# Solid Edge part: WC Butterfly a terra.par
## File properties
Title: WC BUTTERFLY A TERRA
Author: DESYS
Template: Iso Part.par
Last saved by: PIM_1
Revision: 17
Application: Solid Edge
Tipo di contenuto documento: 0
Accuracy: 0,990
Document Number: 4008
Revision: 0
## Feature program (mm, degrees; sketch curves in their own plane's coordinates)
sketch for "unnamed Protrusion 1" plane through (10.8674, 0, 10.8674) normal (0, -1, 0) x-axis (1, 0, 0)
  line (-193.3674, -268.3674) -> (171.6326, -268.3674)
  line (171.6326, -268.3674) -> (171.6326, 216.6326)
  arc centre (131.6326, 216.6326) radius 40 from (131.6326, 256.6326) to (171.6326, 216.6326) cw
  line (131.6326, 256.6326) -> (-153.3674, 256.6326)
  arc centre (-153.3674, 216.6326) radius 40 from (-193.3674, 216.6326) to (-153.3674, 256.6326) cw
  line (-193.3674, 216.6326) -> (-193.3674, -268.3674)
  dimension (linear) = 193.3674
extrude "unnamed Protrusion 1" add finite 40 along -normal
sketch for "ProtrusioneEstrusa_2" plane through (0, 420, 0) normal (0, -1, 0) x-axis (1, 0, 0)
  line (-72.5, 142.5) -> (72.5, 142.5)
  arc centre (72.5, 102.5) radius 40 from (72.5, 142.5) to (112.5, 102.5) cw
  line (112.5, 102.5) -> (112.5, -257.5)
  line (112.5, -257.5) -> (-112.5, -257.5)
  line (-112.5, -257.5) -> (-112.5, 102.5)
  arc centre (-72.5, 102.5) radius 40 from (-112.5, 102.5) to (-72.5, 142.5) cw
  dimension (linear) = 112.5
extrude "ProtrusioneEstrusa_2" add finite 35 along +normal  Profile_Plane1_Distance = 420 mm
sketch for "ProtrusioneEstrusa_3" plane through (0, 0, 0) normal (1, 0, 0) x-axis (0, 1, 0)
  line (40, -257.5) -> (385, -257.5)
  line (385, 122.5) -> (385, -257.5)
  arc centre (364.5582, 396.4689) radius 274.7305 from (170, 202.5) to (385, 122.5) ccw
  arc centre (48.0094, 60.3605) radius 187.3108 from (40, 247.5) to (170, 202.5) cw
  line (40, 247.5) -> (40, -257.5)
extrude "ProtrusioneEstrusa_3" add finite 325 symmetric
sketch for "unnamed Cutout 1" plane through (0, 210, -257.5) normal (0, 0, -1) x-axis (1, 0, 0)
  line (-92.5, -175) -> (-205.9935, -175)
  line (-162.5, 170) -> (-92.5, -175)
  line (-162.5, 170) -> (-200.7213, 170)
extrude "unnamed Cutout 1" cut through along -normal
mirror "unnamed Mirror 1" of "unnamed Cutout 1" about plane through (0, 0, 0) normal (1, 0, 0)
extrude "unnamed Cutout 2" cut through
fillet "Rotondo_2" radius 30  VertexRadius1 = 30 mm; VertexRadius2 = 55 mm
mirror "unnamed Mirror 2" of "Rotondo_2" about plane through (0, 0, 0) normal (1, 0, 0)
fillet "unnamed Round 1"
fillet "Rotondo_4" radius 25
fillet "Rotondo_5" radius 30
fillet "Rotondo_6" radius 10
sketch for "ScavoEstrusione_3" plane through (0, 0, 0) normal (0, -1, 0) x-axis (0, 0, 1)
  line (-67.5, -137.5) -> (192.5, -137.5)
  arc centre (192.5, -107.5) radius 30 from (192.5, -137.5) to (222.5, -107.5) ccw
  line (222.5, -107.5) -> (222.5, 107.5)
  arc centre (192.5, 107.5) radius 30 from (192.5, 137.5) to (222.5, 107.5) cw
  line (192.5, 137.5) -> (-67.5, 137.5)
  arc centre (-67.5, 107.5) radius 30 from (-67.5, 137.5) to (-97.5, 107.5) ccw
  line (-97.5, 107.5) -> (-97.5, -107.5)
  arc centre (-67.5, -107.5) radius 30 from (-97.5, -107.5) to (-67.5, -137.5) ccw
extrude "ScavoEstrusione_3" cut finite 90 along -normal  Treatment1_DraftAngle = 10 deg
lofted cutout "unnamed LoftedCutout 1"
sketch for "ScavoEstrusione_4" plane through (0, 210, -257.5) normal (0, 0, -1) x-axis (1, 0, 0)
  line (97.5, -210) -> (97.5, -183.2591)
  arc centre (122.6454, -152.1511) radius 40 from (97.5, -183.2591) to (83.4442, -144.1973) cw
  line (83.4442, -144.1973) -> (142.9948, 149.3023)
  arc centre (187.0962, 140.3542) radius 45 from (167.5, 180.8633) to (142.9948, 149.3023) ccw
  line (167.5, 195) -> (167.5, 180.8633)
  line (167.5, 195) -> (-167.5, 195)
  line (-167.5, 195) -> (-167.5, 180.8633)
  arc centre (-187.0962, 140.3542) radius 45 from (-142.9948, 149.3023) to (-167.5, 180.8633) ccw
  line (-142.9948, 149.3023) -> (-83.4442, -144.1973)
  arc centre (-122.6454, -152.1511) radius 40 from (-83.4442, -144.1973) to (-97.5, -183.2591) cw
  line (-97.5, -183.2591) -> (-97.5, -210)
extrude "ScavoEstrusione_4" cut finite 125 along -normal
sketch for "ScavoEstrusione_5" plane through (0, 217.5, -132.5) normal (0, 0, -1) x-axis (1, 0, 0)
  line (-97.5, -175.7591) -> (-97.5, -202.5)
  arc centre (-122.6454, -144.6511) radius 40 from (-83.4442, -136.6973) to (-97.5, -175.7591) cw
  line (-123.9672, 63.0233) -> (-83.4442, -136.6973)
  arc centre (-47.5, 127.4653) radius 100 from (-123.9672, 63.0233) to (-50.1353, 27.5) ccw
  line (-50.1353, 27.5) -> (44.8648, 27.5)
  arc centre (47.5, 127.4653) radius 100 from (44.8648, 27.5) to (123.9672, 63.0233) ccw
  line (83.4442, -136.6973) -> (123.9672, 63.0233)
  arc centre (122.6454, -144.6511) radius 40 from (97.5, -175.7591) to (83.4442, -136.6973) cw
  line (97.5, -202.5) -> (97.5, -175.7591)
extrude "ScavoEstrusione_5" cut finite 175 along -normal
fillet "Rotondo_7" radius 30
fillet "Rotondo_8" radius 10  Radii2 = 10 mm
fillet "Rotondo_9" radius 60
sketch for "unnamed Protrusion 2" #1 plane through (0, 210, -257.5) normal (0, 0, -1) x-axis (1, 0, 0)
  line (-87.5, -210) -> (-83.4442, -144.1973)
  line (-83.4442, -144.1973) -> (-91.6082, -144.1973)
  line (-91.6082, -144.1973) -> (-97.0298, -168.4595)
  line (-97.0298, -168.4595) -> (-100.685, -182.4226)
  line (-100.685, -182.4226) -> (-100.685, -210)
  line (-87.5, -210) -> (-100.685, -210)
sketch for "unnamed Protrusion 2" #2 plane through (0, 210, -257.5) normal (0, 0, -1) x-axis (1, 0, 0)
  line (87.5, -210) -> (83.4442, -144.1973)
  line (83.4442, -144.1973) -> (91.6082, -144.1973)
  line (91.6082, -144.1973) -> (97.0298, -168.4595)
  line (97.0298, -168.4595) -> (100.685, -182.4226)
  line (100.685, -182.4226) -> (100.685, -210)
  line (87.5, -210) -> (100.685, -210)
extrude "unnamed Protrusion 2" add through along -normal
sketch for "ScavoEstrusione_6" plane through (0, 420, -57.5) normal (0, 1, 0) x-axis (1, 0, 0)
  line (-87.5, -100) -> (87.5, -100)
  line (87.5, -100) -> (87.5, -145)
  arc centre (62.5, -145) radius 25 from (62.5, -170) to (87.5, -145) ccw
  line (62.5, -170) -> (-62.5, -170)
  arc centre (-62.5, -145) radius 25 from (-87.5, -145) to (-62.5, -170) ccw
  line (-87.5, -145) -> (-87.5, -100)
extrude "ScavoEstrusione_6" cut finite 70 along -normal
replace surface "unnamed ReplaceSurface 1"
replace surface "unnamed ReplaceSurface 2"
sketch for "ProtrusioneEstrusa_7" plane through (0, 210, -257.5) normal (0, 0, -1) x-axis (1, 0, 0)
  line (-87.5, -210) -> (87.5, -210)
  line (86.2673, -190) -> (87.5, -210)
  line (-86.2673, -190) -> (86.2673, -190)
  line (-86.2673, -190) -> (-87.5, -210)
extrude "ProtrusioneEstrusa_7" add finite 30 along -normal
sketch for "ProtrusioneEstrusa_8" plane through (0, 410, -57.5) normal (0, 1, 0) x-axis (1, 0, 0)
  line (-35, -150) -> (35, -150)
  arc centre (35, -130) radius 20 from (55, -130) to (35, -150) cw
  line (55, -130) -> (55, -30)
  arc centre (35, -30) radius 20 from (35, -10) to (55, -30) cw
  line (35, -10) -> (-35, -10)
  arc centre (-35, -30) radius 20 from (-55, -30) to (-35, -10) cw
  line (-55, -30) -> (-55, -130)
  arc centre (-35, -130) radius 20 from (-35, -150) to (-55, -130) cw
  dimension (linear) = 35
  dimension (linear) = 55
extrude "ProtrusioneEstrusa_8" add through along -normal  Profile_Plane1_Distance = 10 mm; Treatment1_DraftAngle = 5 deg
fillet "Rotondo_10" radius 60
sketch for "ProtrusioneEstrusa_9" plane through (0, 210, -142.5) normal (0, 0, -1) x-axis (1, 0, 0)
  circle centre (0, -30.1) radius 50
extrude "ProtrusioneEstrusa_9" add through along -normal  Profile_Plane1_Distance = 115 mm
sketch for "ProtrusioneEstrusa_10" plane through (0, 210, -237.5) normal (0, 0, -1) x-axis (1, 0, 0)
  line (-40, 155) -> (-40, 186.0971)
  line (40, 155) -> (40, 186.0971)
extrude "ProtrusioneEstrusa_10" add through along -normal  Profile_Plane1_Distance = 20 mm
sketch for "ScavoEstrusione_7" plane through (0, 55, -237.5) normal (0, 0, -1) x-axis (1, 0, 0)
  circle centre (0, 0) radius 27.5
extrude "ScavoEstrusione_7" cut finite 70 along -normal
sketch for "ScavoEstrusione_8" plane through (0, 240.1, -142.5) normal (0, 0, -1) x-axis (1, 0, 0)
  circle centre (0, 0) radius 40
extrude "ScavoEstrusione_8" cut finite 105 along -normal
sketch for "ScavoEstrusione_9" plane through (0, 180, 52.5) normal (0, -1, 0) x-axis (0, 0, 1)
  line (20, -50) -> (-55, -50)
  arc centre (-55, -35) radius 15 from (-70, -35) to (-55, -50) ccw
  line (-70, -35) -> (-70, 35)
  arc centre (-55, 35) radius 15 from (-55, 50) to (-70, 35) ccw
  line (-55, 50) -> (20, 50)
extrude "ScavoEstrusione_9" cut finite 150 along -normal
sketch for "unnamed Cutout 3" plane through (0, 330, 35.1247) normal (0, -1, 0) x-axis (0, 0, 1)
  line (-72.6247, 40) -> (-85.0909, 40)
  line (-85.0909, 40) -> (-85.0909, -40)
  line (-85.0909, -40) -> (-72.6247, -40)
  line (-72.6247, -40) -> (-72.6247, 40)
extrude "unnamed Cutout 3" cut to key point along +normal
sketch for "ScavoEstrusione_11" plane through (0, 275.05, -37.5) normal (0, 0, -1) x-axis (1, 0, 0)
  line (-34.546, -42.1793) -> (34.546, -42.1793)
  line (34.546, -42.1793) -> (34.546, -54.1793)
  line (34.546, -54.1793) -> (-34.546, -54.1793)
  line (-34.546, -42.1793) -> (-34.546, -54.1793)
extrude "ScavoEstrusione_11" cut finite 30 along -normal
fillet "Rotondo_11" radius 20
sketch for "unnamed Protrusion 3" plane through (0, 210, -257.5) normal (0, 0, -1) x-axis (1, 0, 0)
  line (-107.5, 195) -> (-127.919, 75)
  dimension (linear) = 127.919
extrude "unnamed Protrusion 3" add through along -normal
mirror "unnamed Mirror 3" of "unnamed Protrusion 3" about plane through (0, 0, 0) normal (1, 0, 0)
extrude "unnamed Protrusion 4" add through
fillet "Rotondo_12" radius 10
fillet "Rotondo_13" radius 10
fillet "Rotondo_14" radius 30
fillet "Rotondo_15" radius 3
fillet "Rotondo_16" radius 20
fillet "Rotondo_17" radius 30
fillet "Rotondo_18" radius 20
fillet "Rotondo_19" radius 5
fillet "Rotondo_20" radius 3
fillet "Rotondo_21" radius 30
fillet "Rotondo_22" radius 15
fillet "Rotondo_23" radius 10
sketch for "Foro_1" plane through (0, 0, -3.5) normal (0, -1, 0) x-axis (0, 0, 1)
  hole centre (-159, -77.5) bore radius 7.5
hole "Foro_1" diameter 15 finite
sketch for "unnamed Hole 1" plane through (0, 0, -3.5) normal (0, -1, 0) x-axis (0, 0, 1)
  hole centre (-159, 77.5) bore radius 7.5
hole "unnamed Hole 1" finite
pattern "unnamed Pattern 1" of "Foro_1", "unnamed Hole 1"
fillet "Rotondo_24" radius 3
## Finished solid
Body 1: solid body, 254 faces, 607 edges, 359 vertices.
  Faces by surface: cylinder 84, blend 59, plane 57, torus 35, spline 9, cone 8, sphere 2
  Edges by curve: line 220, circle 204, intersection 125, curve on surface 40, ellipse 18
Bounding box of the edges (mm; curved faces can reach further): 365.000 x 420.000 x 525.000, from (-182.5, 0, -257.5) to (182.5, 420, 267.5).
Cylindrical faces by radius (mm): R3 x19, R5 x2, R7.5 x2, R10 x19, R15 x2, R20 x6, R25 x5, R27.5 x1, R30 x9, R40 x8, R50 x2, R60 x5, R100 x2, R187.3108 x1, R274.7305 x1
Conical faces (half-angle, radius in mm at the cone's reference point): 5 deg R20 x4, 10 deg R30 x4
Toroidal faces (ring radius, tube radius in mm): R7 r3 x6, R10.5 r3 x2, R13 r3 x2, R28 r3 x2, R30 r10 x2, R33 r3 x4, R35 r5 x1, R37 r3 x4, R38.391 r10 x4, R40 r10 x1, R40 r60 x2, R45 r5 x1, R60 r20 x2, R70 r60 x2
Spherical faces by radius (mm): R3 x2
Planar faces by outward normal: +x 6, +y 6, +z 7, -x 6, -y 7, -z 9, oblique 16
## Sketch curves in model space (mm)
arc centre (0, 81.9548, 2.1758) radius 100 from (0, 90, -97.5) through (0, 148.3912, -72.5651) to (0, 180, -17.5)
arc centre (0, 80.0013, 123.0011) radius 100 from (0, 90, 222.5) through (0, 156.2723, 187.6751) to (0, 180, 122.5)
arc centre (47.5, 90.0347, 0) radius 90 from (50, 180, 0) through (112.0295, 152.7718, 0) to (137.5, 90, 0)
arc centre (-47.5, 90.0347, 0) radius 90 from (-137.5, 90, 0) through (-112.0295, 152.7718, 0) to (-50, 180, 0)
arc centre (0, 180, 72.5) radius 50 from (-50, 180, 72.5) through (1.4817, 180, 122.478) to (50, 180, 72.5)
line (50, 180, 72.5) -> (50, 180, -2.5)
arc centre (35, 180, -2.5) radius 15 from (35, 180, -17.5) through (45.9106, 180, -12.7936) to (50, 180, -2.5)
line (35, 180, -17.5) -> (-35, 180, -17.5)
arc centre (-35, 180, -2.5) radius 15 from (-50, 180, -2.5) through (-45.2936, 180, -13.4106) to (-35, 180, -17.5)
line (-50, 180, -2.5) -> (-50, 180, 72.5)
arc centre (107.5, 90, -67.5) radius 30 from (107.5, 90, -97.5) through (129.3212, 90, -88.0872) to (137.5, 90, -67.5)
line (137.5, 90, -67.5) -> (137.5, 90, 192.5)
arc centre (107.5, 90, 192.5) radius 30 from (137.5, 90, 192.5) through (128.0872, 90, 214.3212) to (107.5, 90, 222.5)
line (107.5, 90, 222.5) -> (-107.5, 90, 222.5)
arc centre (-107.5, 90, 192.5) radius 30 from (-107.5, 90, 222.5) through (-129.3212, 90, 213.0872) to (-137.5, 90, 192.5)
line (-137.5, 90, 192.5) -> (-137.5, 90, -67.5)
arc centre (-107.5, 90, -67.5) radius 30 from (-137.5, 90, -67.5) through (-128.0872, 90, -89.3212) to (-107.5, 90, -97.5)
line (-107.5, 90, -97.5) -> (107.5, 90, -97.5)
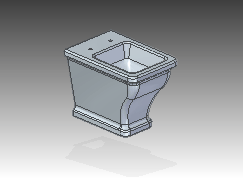
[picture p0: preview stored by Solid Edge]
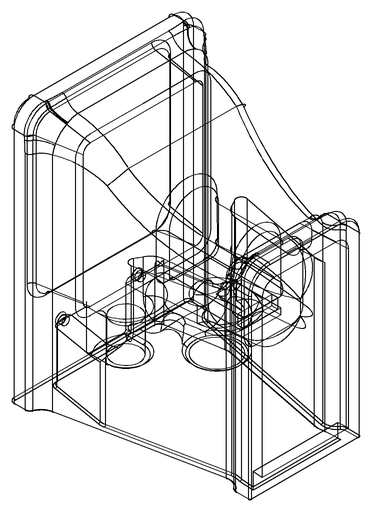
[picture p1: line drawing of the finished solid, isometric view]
